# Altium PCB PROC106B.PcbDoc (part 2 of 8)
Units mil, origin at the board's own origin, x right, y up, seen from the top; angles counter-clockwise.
Board outline 4498.18 x 1060.53 mil, 8 copper layers (Top Layer, GND1, Sig1, PWR1, PWR2, Sig2, GND2, Bottom Layer), stack 69.602 mil thick; 439 components, 327 nets, 1548 pads, 843 vias.
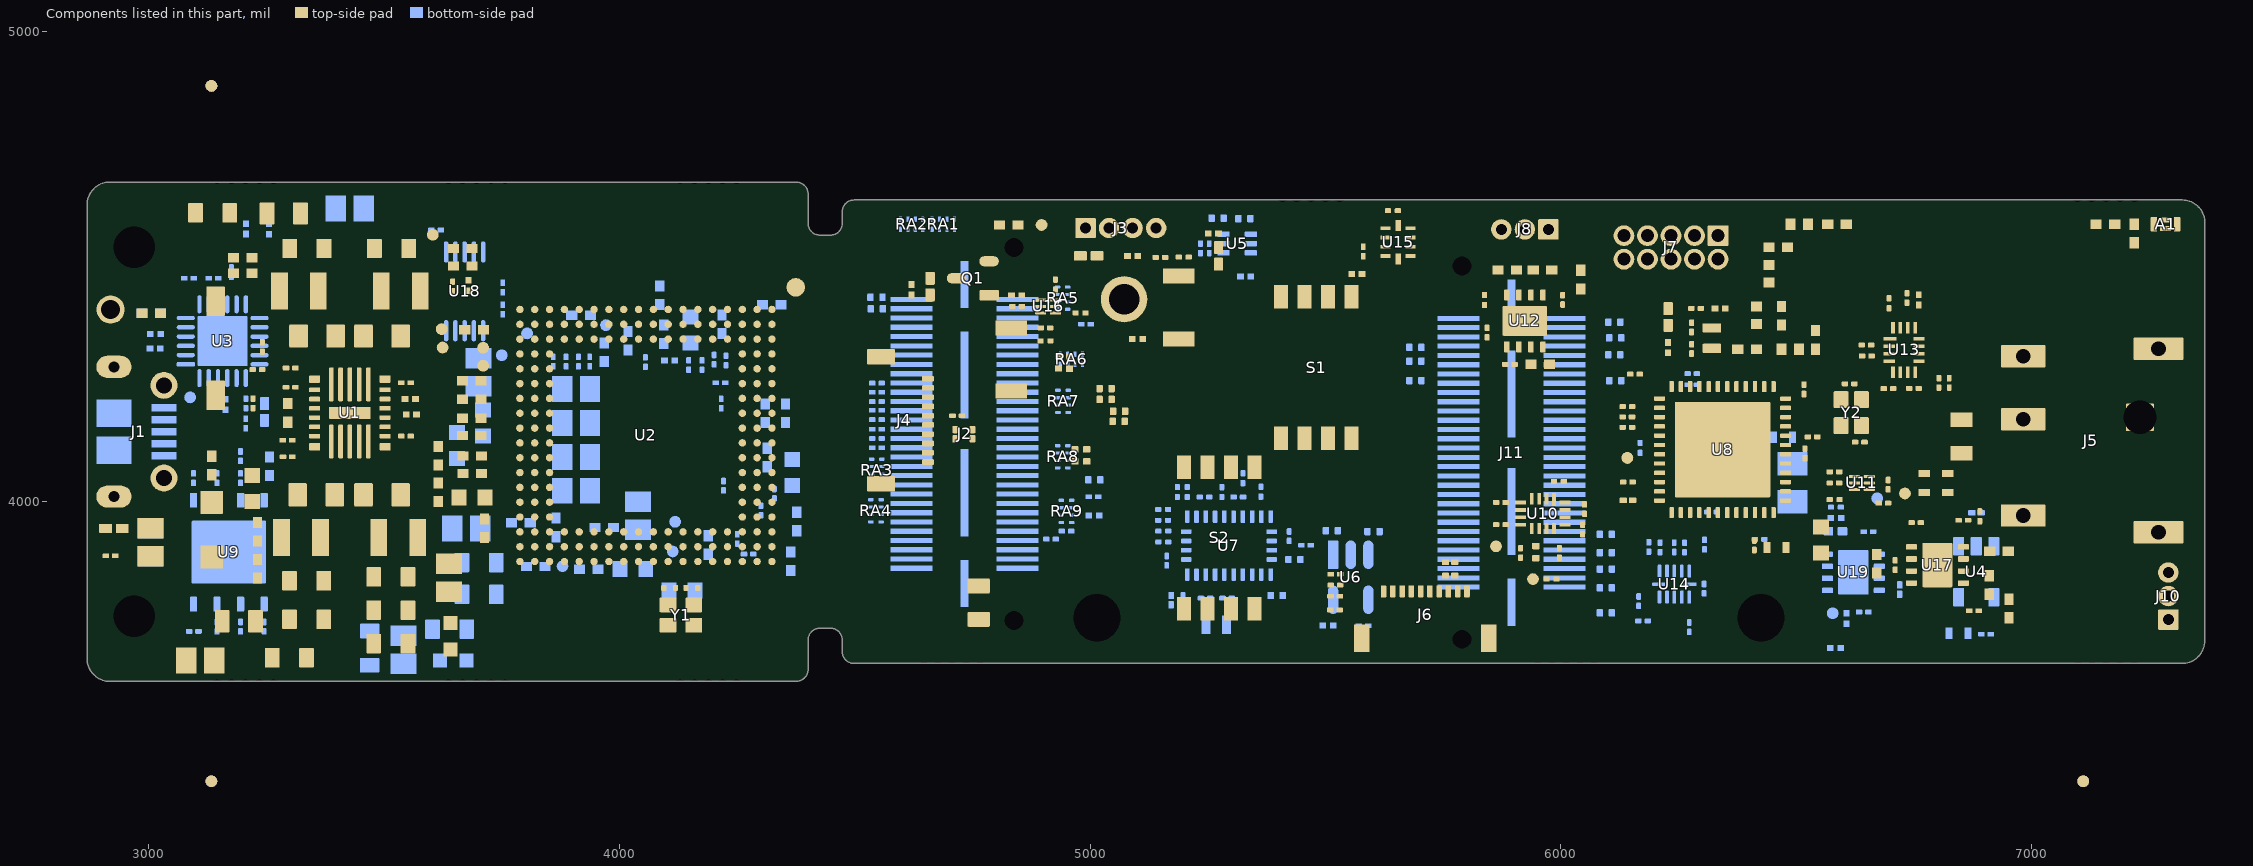
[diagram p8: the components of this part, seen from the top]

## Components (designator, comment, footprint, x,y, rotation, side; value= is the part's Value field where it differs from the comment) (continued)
R122 "RR0306P-103-D" FP-RR0306P-103-D_0201-IPC_C#1 5837.64,4429.06 r270 top
R123 "RC0201JR-070RL" "FP-RC0201JR-070RL_0201 (0603 METRIC)-IPC_C" 5843.14,4359.71 r90 top
R124 "RR0306P-103-D" FP-RR0306P-103-D_0201-IPC_C#1 4905.31,4342.12 r0 top
R125 "RR0306P-103-D" FP-RR0306P-103-D_0201-IPC_C#1 5198.85,4520.03 r180 top
R126 "CRCW040261R9FKED" 0402L 5960.92,4492.48 r0 top value=61.9
R127 "RC0201JR-070RL" "FP-RC0201JR-070RL_0201 (0603 METRIC)-IPC_C" 6649.8,4310 r0 top
R128 "RC0201JR-070RL" "FP-RC0201JR-070RL_0201 (0603 METRIC)-IPC_C" 6695.72,4240.71 r180 top
R129 "RC0201JR-070RL" "FP-RC0201JR-070RL_0201 (0603 METRIC)-IPC_C" 5149.26,4519.45 r180 top
R130 "AC0201FR-0720RL" FP-AC0201FR-0720RL_0201-IPC_C 4547.27,4134.63 r0 bottom
R131 "RC0201JR-070RL" "FP-RC0201JR-070RL_0201 (0603 METRIC)-IPC_C" 6321.17,3978.41 r180 bottom
R132 "AC0201FR-0720RL" FP-AC0201FR-0720RL_0201-IPC_C 4547.27,4154.34 r0 bottom
R133 "AC0201FR-0720RL" FP-AC0201FR-0720RL_0201-IPC_C 4547.27,4174.75 r0 bottom
R134 "RR0306P-103-D" FP-RR0306P-103-D_0201-IPC_C#1 6889.73,3969.51 r90 top
R135 "AC0201FR-0720RL" FP-AC0201FR-0720RL_0201-IPC_C 4547.27,4194.78 r0 bottom
R136 "RC0201JR-070RL" "FP-RC0201JR-070RL_0201 (0603 Metric)-IPC_C" 6749.82,4241 r0 top
R137 "AC0201FR-0720RL" FP-AC0201FR-0720RL_0201-IPC_C 4547.27,4213.11 r0 bottom
R138 "AC0201FR-0720RL" FP-AC0201FR-0720RL_0201-IPC_C 4547.27,4233.08 r0 bottom
R139 "RC0201JR-070RL" "FP-RC0201JR-070RL_0201 (0603 Metric)-IPC_C" 6824.81,4252.99 r270 top
R140 "AC0201FR-0720RL" FP-AC0201FR-0720RL_0201-IPC_C 4547.27,4252.4 r0 bottom
R141 "RC0201FR-074K99L" 0201L 6760.03,4429.26 r90 top value=4.99k
R142 "RC0201JR-070RL" "FP-RC0201JR-070RL_0201 (0603 Metric)-MFG" 4992.71,4098.76 r270 top
R143 "RC0201JR-070RL" "FP-RC0201JR-070RL_0201 (0603 Metric)-MFG" 4967.77,4098.76 r270 top
R144 "RC0201JR-070RL" "FP-RC0201JR-070RL_0201 (0603 Metric)-MFG" 5061.58,4192.66 r0 top
R145 "RC0201JR-070RL" "FP-RC0201JR-070RL_0201 (0603 Metric)-MFG" 5060.48,4171.22 r0 top
R146 "RC0201JR-070RL" "FP-RC0201JR-070RL_0201 (0603 Metric)-MFG" 5032.8,4217.79 r0 top
R147 "RC0201JR-070RL" "FP-RC0201JR-070RL_0201 (0603 Metric)-MFG" 5032.8,4240.79 r0 top
R148 "RC0201JR-070RL" "FP-RC0201JR-070RL_0201 (0603 Metric)-MFG" 4932.76,4296.62 r90 top
R149 "RC0201JR-070RL" "FP-RC0201JR-070RL_0201 (0603 Metric)-MFG" 4956.17,4295.87 r90 top
R150 "RC0201JR-070RL" "FP-RC0201JR-070RL_0201 (0603 Metric)-MFG" 6113.61,4381.76 r0 bottom
R151 "RC0201JR-070RL" "FP-RC0201JR-070RL_0201 (0603 Metric)-MFG" 6115.41,4348.48 r0 bottom
R152 "RC0201JR-070RL" "FP-RC0201JR-070RL_0201 (0603 Metric)-MFG" 5690.93,4328.4 r0 bottom
R153 "RC0201JR-070RL" "FP-RC0201JR-070RL_0201 (0603 Metric)-MFG" 6113.32,4312.59 r0 bottom
R154 "RC0201JR-070RL" "FP-RC0201JR-070RL_0201 (0603 Metric)-MFG" 5690.93,4298.93 r0 bottom
R155 "RC0201JR-070RL" "FP-RC0201JR-070RL_0201 (0603 Metric)-MFG" 6115.55,4257.57 r0 bottom
R157 "RC0201JR-070RL" "FP-RC0201JR-070RL_0201 (0603 Metric)-MFG" 5690.93,4257.72 r0 bottom
R158 "ERJ-1GNF8252C" FP-ERJ-1GNF8252C_0201-IPC_C 4175.56,4290.74 r270 bottom value=82.5k
R159 "ERJ-1GNJ751C" FP-ERJ-1GNJ751C_0201-IPC_C 4201.23,4302.15 r90 bottom value=750
R160 "RC0201JR-070RL" "FP-RC0201JR-070RL_0201 (0603 METRIC)-IPC_C" 6262.64,3903.15 r90 bottom
R161 "RC0201JR-070RL" "FP-RC0201JR-070RL_0201 (0603 METRIC)-IPC_C" 6141.18,4158.46 r0 top
R166 "RC0201JR-070RL" "FP-RC0201JR-070RL_0201 (0603 METRIC)-IPC_C" 6240.62,3903.59 r90 bottom
R168 "RC0201JR-070RL" "FP-RC0201JR-070RL_0201 (0603 METRIC)-IPC_C" 6186.75,3904.39 r90 bottom
R170 "ERJ-1GNF8252C" FP-ERJ-1GNF8252C_0201-IPC_C 4214.74,4253.13 r180 bottom value=82.5k
R171 "ERJ-1GNJ751C" FP-ERJ-1GNJ751C_0201-IPC_C 4226.45,4300.41 r90 bottom value=750
R172 "ERJ-1GNF8252C" FP-ERJ-1GNF8252C_0201-IPC_C 3206.71,4209.45 r270 bottom value=82.5k
R174 "ERJ-1GNF7871C" FP-ERJ-1GNF7871C_0201-IPC_C 4147.23,4290.74 r270 bottom value=7.87k
R176 "ERJ-1GNF7871C" FP-ERJ-1GNF7871C_0201-IPC_C 3221.71,4209.45 r270 top value=7.87k
R177 "RR0306P-103-D" FP-RR0306P-103-D_0201-IPC_C#1 4979.62,4401.5 r180 top
R178 "RR0306P-103-D" FP-RR0306P-103-D_0201-IPC_C#1 4926.29,4461.7 r270 top
R180 "ERJ-1GNF4701C" FP-ERJ-1GNF4701C_0201-IPC_C 6165.19,3789.15 r270 bottom
R181 "ERJ-1GNF4701C" FP-ERJ-1GNF4701C_0201-IPC_C 5520.05,3770.65 r180 top
R182 "RC0201JR-070RL" "FP-RC0201JR-070RL_0201 (0603 METRIC)-IPC_C" 4717.71,4183.18 r180 top
R183 "RC0201JR-070RL" "FP-RC0201JR-070RL_0201 (0603 METRIC)-IPC_C" 5520.61,3799.62 r180 top
R184 "RC0201JR-070RL" "FP-RC0201JR-070RL_0201 (0603 METRIC)-IPC_C" 5521.16,3823.28 r180 top
R185 "RC0201JR-070RL" "FP-RC0201JR-070RL_0201 (0603 METRIC)-IPC_C" 5521,3846.49 r180 top
R186 "RC0201JR-070RL" "FP-RC0201JR-070RL_0201 (0603 Metric)-MFG" 6095.54,3931.22 r0 bottom
R187 "RC0201JR-070RL" "FP-RC0201JR-070RL_0201 (0603 Metric)-MFG" 6095.54,3892.26 r0 bottom
R188 "RC0201JR-070RL" "FP-RC0201JR-070RL_0201 (0603 Metric)-MFG" 6095.54,3857.41 r0 bottom
R189 "RC0201JR-070RL" "FP-RC0201JR-070RL_0201 (0603 Metric)-MFG" 6095.54,3817.56 r0 bottom
R190 "RC0201JR-070RL" "FP-RC0201JR-070RL_0201 (0603 Metric)-MFG" 6095.54,3764.53 r0 bottom
RA1 "EXB-18VR000X" FP-EXB-18VR000X_0502-MFG 4688.09,4589.75 r0 bottom
RA2 "EXB-18VR000X" FP-EXB-18VR000X_0502-MFG 4620.86,4589.75 r0 bottom
RA3 "EXB-18VR000X" FP-EXB-18VR000X_0502-MFG 4546.77,4067.23 r90 bottom
RA4 "EXB-18VR000X" FP-EXB-18VR000X_0502-MFG 4545.1,3981.11 r90 bottom
RA5 "EXB-18VR000X" FP-EXB-18VR000X_0502-MFG 4941.51,4432.71 r90 bottom locked
RA6 "EXB-18VR000X" FP-EXB-18VR000X_0502-MFG 4960.21,4302.91 r0 bottom
RA7 "EXB-18VR000X" FP-EXB-18VR000X_0502-MFG 4942.52,4213.65 r90 bottom locked
RA8 "EXB-18VR000X" FP-EXB-18VR000X_0502-MFG 4941.86,4095.87 r90 bottom locked
RA9 "EXB-18VR000X" FP-EXB-18VR000X_0502-MFG 4949.85,3979.76 r90 bottom locked
S1 "218-4LPST" SW_218-4LPST 5480.37,4285.46 r90 top
S2 "218-4LPST" SW_218-4LPST 5274.37,3923.46 r90 top locked
S3 "CHS-01TA" FP-CHS-01TA_SMT_SW_5MM4_2MM5-MFG 3142.31,4326.42 r90 top
SW2 "B3U-1000P" SW_B3U-1000P 4832.84,4302.77 r270 top
SW3 "B3U-1000P" SW_B3U-1000P 5188.73,4412.81 r270 top
TP2 "TESTPOINT" TP_25MIL-SMT 4113.44,3894.78 r180 bottom
TP3 "TESTPOINT" TP_25MIL-SMT 4118.39,3957.8 r180 bottom
TP4 "TESTPOINT" TP_25MIL-SMT 6671.71,4007.65 r180 bottom
TP5 "TESTPOINT" TP_25MIL-SMT 3603.84,4567.52 r180 top
TP6 "TESTPOINT" TP_25MIL-SMT 3750.12,4311.58 r90 bottom
TP7 "TESTPOINT" TP_25MIL-SMT 3804,4358 r0 bottom
TP8 "TESTPOINT" TP_25MIL-SMT 3710.6,4327.53 r0 top
TP9 "TESTPOINT" TP_25MIL-SMT 3710.6,4289.4 r0 top
TP10 "TESTPOINT" TP_25MIL-SMT 6577.18,3763.46 r270 bottom
TP11 "TP_SM_1MM" TP_SM_1MM 4374.76,4455.87 r180 top
TP12 "TESTPOINT" TP_VIA_060RND040 2919.28,4408.64 r90 top
TP13 "TESTPOINT" TP_25MIL-SMT 4896.84,4588.36 r270 top
TP14 "TESTPOINT" TP_25MIL-SMT 3971.52,4375.57 r270 bottom
TP15 "TESTPOINT" TP_25MIL-SMT 6730.81,4018 r90 top
TP16 "TESTPOINT" TP_25MIL-SMT 6141.18,4093.46 r180 top
TP17 "TESTPOINT" TP_25MIL-SMT 3879.25,3863.39 r180 bottom
TP18 "TESTPOINT" TP_25MIL-SMT 3622.56,4367.08 r180 top
TP19 "TESTPOINT" TP_25MIL-SMT 3624.53,4327.96 r180 top
TP20 "4953" FP-4953_HDR1-MFG 5072.16,4430.47 r180 bottom locked
TP26 "TESTPOINT" TP_25MIL-SMT 3088.22,4222.02 r0 bottom
TP27 "TESTPOINT" TP_25MIL-SMT 5862.18,3905.74 r270 top
TP46 "TESTPOINT" TP_25MIL-SMT 5940.71,3836.09 r270 top
U1 "LP87524JRNFRQ1" RNF0026C 3427.48,4189 r180 top
U2 "AWR1843AoPBGALP" ALP0180A-MFG 4056.48,4141.13 r180 top
U3 "CP2105-F01-GMR" FP-CP2105-F01-GMR_QFN24-EP-IPC_A 3157.31,4341.42 r0 bottom
U4 "TPS79330DBVR" DBV0005A_N 6882.18,3851.63 r270 bottom
U5 "TMP112AQDRLRQ1" DRL0006A 5312.36,4548.71 r180 bottom
U6 "CAT24C08TDI-GT3" FP-CAT24C08TDI-GT3_TSOT-23-5-IPC_A 5553.54,3840.01 r270 bottom
U7 "BNO085" FP-BNO085_LGA28-MFG 5294.88,3907.22 r270 bottom
U8 "CC2642R1FRGZR" RGZ0048A 6343.38,4111.11 r270 top
U9 "MX25V1635FZNQ" WSON-8L_6x5MM_EP 3170.35,3893.29 r90 bottom locked
U10 "TCA6408ARSVR" RSV0016A 5961.56,3975.2 r270 top
U11 "SN74LVC1G3157DSFR" DSF0006A 6639.32,4040.29 r180 top
U12 "TCAN1042HGVDRBRQ1" DRB0008F 5923.44,4384.46 r90 top
U13 "TS3A5018RSVR" RSV0016A 6728.94,4322.76 r0 top
U14 "TXB0104QRUTRQ1" RUT0012A 6241.04,3825.36 r90 bottom
U15 "TS5A23157RSER" RSE0010A 5654.19,4551.79 r180 top
U16 "SN74LVC1G11DSFR" DSF0006A-MFG 4910.54,4415.28 r180 top
U17 "TCAN1042HGVDRBRQ1" DRB0008F 6799.78,3866 r0 top
U18 "TS5A23157QDGSRQ1" DGS0010A_L 3671.35,4447.33 r270 bottom
U19 "TPS2115ADRBR" DRB0008B 6621.18,3850.46 r0 bottom
Y1 "FW4000044Q" FP-FW4000044Q_4-SMD-2.0x1.6mm-MFG 4130.76,3759.63 r180 top
Y2 "CX2016DB48000C0WPLA2" FP-CX2016DB48000C0WPLA2_SMD4-MFG 6616.71,4189.85 r270 top
Y3 "ABS05W-32.768KHZ-D-2-T" FP-ABS05W-32.768KHZ-D-2-T_XTAL_SMT_1MM6_1MM0-MFG 6320.71,4347.93 r270 top
Y4 "ABS05W-32.768KHZ-D-2-T" FP-ABS05W-32.768KHZ-D-2-T_XTAL_SMT_1MM6_1MM0-MFG 5267.82,3738.88 r0 bottom
ZZ1 "This Assembly Note is for PCB labels only" AssemblyNoteLabel 2349.62,2814.36 r0 top
ZZ2 "These assemblies are ESD sensitive, ESD precautions shall be observed." AssemblyNote 2346.49,2738.89 r0 top
ZZ3 "These assemblies must be clean and free from flux and all contaminants. Use of no clean flux is not acceptable." AssemblyNote 2346.43,2653.5 r0 top
ZZ4 "These assemblies must comply with workmanship standards IPC-A-610 Class 2, unless otherwise specified." AssemblyNote 2343.34,2567.2 r0 top
ZZ5.1 "Cut the thermal pad(Part Number#GPVOUS-0.125-AC-0816) for the shape and size of the inner surface of the heatsink(Part Number#MCH065) and paste it on the inner surface of the heatsink;" AssemblyNote 2340.76,2492.7 r0 top
ZZ5.2 "Bring the heatsink onto the PCB bottom side (Opposite side of AOP device). Match the teeth in the heatsink with break-away area in the PCB and press the heatsink onto the PCB slightly so as thermal pad is spread all over the area" AssemblyNote 2343.41,2409 r0 top

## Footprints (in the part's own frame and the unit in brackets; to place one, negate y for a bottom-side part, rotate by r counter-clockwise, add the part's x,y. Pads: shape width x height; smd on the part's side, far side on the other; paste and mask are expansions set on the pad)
0201L [mm] "Data from Kemet datasheet CC101_COM dated 7/28/11"
  rect 0.36x0.32 smd mask+0.048: 1(-0.28,0) 2(0.28,0)
  body extent -0.31,-0.16 0.31,0.16, height 0.26
0402_070 [mil] "SMD, 2-Leads, Body 1.2x0.7mm, Height 0.7mm"
  rect 15x24 smd: 1(-20,0) 2(20,0)
  body extent -24,-14 24,14, height 28
0402L [mm] "0402 from SM-752 data"
  rect 0.6x0.5 smd: 1(-0.5,0) 2(0.5,0)
  body extent -0.55,-0.3 0.55,0.3, height 0.6
0402S [mil] "Based on C0402S footprint from PADS legacy"
  rect 15x24 smd: 1(-20,0) 2(20,0)
  body extent -22,-12 22,12, height 24
0603_HV [mil] "Ernesto recommended land pattern.  26 mil between pads."
  rect 30x30 smd: 1(-28,0) 2(28,0)
  silkscreen extent -52,-24 52,24, body extent -34,-19 34,19, height 39
0603L [mm] "0603 from SM-752 data"
  rect 0.8x0.85 smd: 1(-0.7,0) 2(0.7,0)
  silkscreen extent -0.07,-0.33 0.07,0.33, body extent -0.87,-0.47 0.87,0.47, height 1
0805_HV [mil] "0805 with 30mil clearance between pads"
  rect 50x63 smd: 1(-40,0) 2(40,0)
  silkscreen extent -74,-40 74,40, body extent -43,-29 43,29, height 57
0805_HV1 [mm] "Custom footprint based on analyzing multiple manufacturer recommendations"
  rrect10% 1x1.25 smd: 1(-1,0) 2(1,0)
  silkscreen extent -0.2,-0.75 0.2,0.75, body extent -1.1,-0.72 1.1,0.73, height 1.45
0805L [mm] "0805 from SM-752 data"
  rect 1.1x1.4 smd: 1(-0.75,0) 2(0.75,0)
  body extent -1.1,-0.72 1.1,0.72, height 1.45
ALP0180A-MFG [mm]
  round 0.4 smd paste+0 mask-1000: A1(-6.8,6.8) A2(-6,6.8) A3(-5.2,6.8) A4(-4.4,6.8) A5(-3.6,6.8) A6(-2.8,6.8) A7(-2,6.8) A8(-1.2,6.8) A9(-0.4,6.8) A10(0.4,6.8) A11(1.2,6.8) A12(2,6.8) A13(2.8,6.8) A14(3.6,6.8) A15(4.4,6.8) A16(5.2,6.8) A17(6,6.8) A18(6.8,6.8) B1(-6.8,6) B2(-6,6) B3(-5.2,6) B4(-4.4,6) B5(-3.6,6) B6(-2.8,6) B7(-2,6) B8(-1.2,6) B9(-0.4,6) B10(0.4,6) B11(1.2,6) B12(2,6) B13(2.8,6) B14(3.6,6) B15(4.4,6) B16(5.2,6) B17(6,6) B18(6.8,6) C1(-6.8,5.2) C2(-6,5.2) C3(-5.2,5.2) C4(-4.4,5.2) C5(-3.6,5.2) C6(-2.8,5.2) C7(-2,5.2) C8(-1.2,5.2) C9(-0.4,5.2) C10(0.4,5.2) C11(1.2,5.2) C12(2,5.2) C13(2.8,5.2) C14(3.6,5.2) C15(4.4,5.2) C16(5.2,5.2) C17(6,5.2) C18(6.8,5.2) D1(-6.8,4.4) D2(-6,4.4) D3(-5.2,4.4) D16(5.2,4.4) D17(6,4.4) D18(6.8,4.4) E1(-6.8,3.6) E2(-6,3.6) E3(-5.2,3.6) E16(5.2,3.6) E17(6,3.6) E18(6.8,3.6) F1(-6.8,2.8) F2(-6,2.8) F3(-5.2,2.8) F16(5.2,2.8) F17(6,2.8) F18(6.8,2.8) G1(-6.8,2) G2(-6,2) G3(-5.2,2) G16(5.2,2) G17(6,2) G18(6.8,2) H1(-6.8,1.2) H2(-6,1.2) H3(-5.2,1.2) H16(5.2,1.2) H17(6,1.2) H18(6.8,1.2) J1(-6.8,0.4) J2(-6,0.4) J3(-5.2,0.4) J16(5.2,0.4) J17(6,0.4) J18(6.8,0.4) K1(-6.8,-0.4) K2(-6,-0.4) K3(-5.2,-0.4) K16(5.2,-0.4) K17(6,-0.4) K18(6.8,-0.4) L1(-6.8,-1.2) L2(-6,-1.2) L3(-5.2,-1.2) L16(5.2,-1.2) L17(6,-1.2) L18(6.8,-1.2) M1(-6.8,-2) M2(-6,-2) M3(-5.2,-2) M16(5.2,-2) M17(6,-2) M18(6.8,-2) N1(-6.8,-2.8) N2(-6,-2.8) N3(-5.2,-2.8) N16(5.2,-2.8) N17(6,-2.8) N18(6.8,-2.8) P1(-6.8,-3.6) P2(-6,-3.6) P3(-5.2,-3.6) P16(5.2,-3.6) P17(6,-3.6) P18(6.8,-3.6) R1(-6.8,-4.4) R2(-6,-4.4) R3(-5.2,-4.4) R16(5.2,-4.4) R17(6,-4.4) R18(6.8,-4.4) T1(-6.8,-5.2) T2(-6,-5.2) T3(-5.2,-5.2) T4(-4.4,-5.2) T5(-3.6,-5.2) T6(-2.8,-5.2) T7(-2,-5.2) T8(-1.2,-5.2) T9(-0.4,-5.2) T10(0.4,-5.2) T11(1.2,-5.2) T12(2,-5.2) T13(2.8,-5.2) T14(3.6,-5.2) T15(4.4,-5.2) T16(5.2,-5.2) T17(6,-5.2) T18(6.8,-5.2) U1(-6.8,-6) U2(-6,-6) U3(-5.2,-6) U4(-4.4,-6) U5(-3.6,-6) U6(-2.8,-6) U7(-2,-6) U8(-1.2,-6) U9(-0.4,-6) U10(0.4,-6) U11(1.2,-6) U12(2,-6) U13(2.8,-6) U14(3.6,-6) U15(4.4,-6) U16(5.2,-6) U17(6,-6) U18(6.8,-6) V1(-6.8,-6.8) V2(-6,-6.8) V3(-5.2,-6.8) V4(-4.4,-6.8) V5(-3.6,-6.8) V6(-2.8,-6.8) V7(-2,-6.8) V8(-1.2,-6.8) V9(-0.4,-6.8) V10(0.4,-6.8) V11(1.2,-6.8) V12(2,-6.8) V13(2.8,-6.8) V14(3.6,-6.8) V15(4.4,-6.8) V16(5.2,-6.8) V17(6,-6.8) V18(6.8,-6.8)
  silkscreen extent -8.3,-7.55 7.55,7.55, body extent -8.05,-8.05 8.05,8.05, height 0.25
APHHS1005_Green [mm] "SMD, 2-Leads, Body 1x0.5mm"
  rrect20% 0.7x0.5 smd: 1(-0.45,0) 2(0.45,0)
  silkscreen extent -0.8,-0.65 1.12,0.65, body extent -0.5,-0.25 0.5,0.25, height 0.5
AssemblyNote [mil] "Assembly Note"
AssemblyNoteLabel [mil] "Assembly Note for PCB Labels"
BRAKE_WAY_HOLES1X2 [mil]
CONN_105017-0001 [mm] "Molex Micro USB-B"
  rect 0.4x1.35 smd: 1(-1.3,1.35) 2(-0.65,1.35) 3(0,1.35) 4(0.65,1.35) 5(1.3,1.35)
  oval 1.2x1.9 hole 0.6 slot 1.3 at 90 deg: 6(-3.5,-1.35) 9(3.5,-1.35)
  rect 1.5x1.9 smd: 7(-1,-1.35) 8(1,-1.35)
  round 1.45 hole 0.85: 10(2.5,1.35) 11(-2.5,1.35)
  Top Layer region: 3.5,-2.3 2.3,-2.3 2.3,-0.4 3.5,-0.4
  Top Layer region: -3.5,-0.4 -2.3,-0.4 -2.3,-2.3 -3.5,-2.3
  silkscreen extent -4.1,-0.2 4.1,1.4, body extent -4.1,-3.93 4.1,1.5, height 2.72
CUI_PJ-051AH [mm] "DC Power Jack, R/A, TH"
  rrect8% 2.4x1.2 hole 0.8 square: 1(-6.3,3.3) 2(-6.3,-5.3) 3(-6.3,-0.1)
  rrect8% 2.7x1.2 hole 0.8 square: 4(1,-6.2) 5(1,3.7)
  rrect7% 1.5x1.5 hole 1.8 square unplated mask+0.102: MH1(0,0)
  body extent -7.75,-6.3 4,3.8, height 7.31
DBV0005A_N [mm] "SOT23, 5-Leads, Body 2.9x1.6mm, Pitch 0.95mm, Lead Span 2.8mm, IPC Medium Density"
  rrect17% 1x0.6 smd: 1(-1.375,0.95) 2(-1.375,0) 3(-1.375,-0.95) 4(1.375,-0.95) 5(1.375,0.95)
  silkscreen extent -0.25,-1.55 0.25,1.55, body extent -1.42,-1.46 1.42,1.46, height 1.09
DFE252012P [mm] "TOKO, Pad sizes increased as per request"
  rect 0.9x2 smd: 1(-1.05,0) 2(1.05,0)
  silkscreen extent -0.3,-1.2 0.3,1.2, body extent -1.35,-1.1 1.35,1.1, height 1.2
DGS0010A_L [mm] "TSSOP, 10-Leads, Body 3x3mm, Pitch 0.5mm, IPC High Density"
  oval 1.15x0.25 smd: 1(-2.125,1) 2(-2.125,0.5) 3(-2.125,0) 4(-2.125,-0.5) 5(-2.125,-1) 6(2.125,-1) 7(2.125,-0.5) 8(2.125,0) 9(2.125,0.5) 10(2.125,1)
  silkscreen extent -2.65,-1.55 0.9,1.55, body extent -2.45,-1.5 2.45,1.5, height 0.96
DRB0008B [mm] "SON, 8-Leads, Body 3x3mm, Pitch 0.65mm, Thermal Pad 2.4x1.65mm, TI Recommended"
  rrect33% 0.6x0.3 smd: 1(-1.4,0.975) 2(-1.4,0.325) 3(-1.4,-0.325) 4(-1.4,-0.975) 5(1.4,-0.975) 6(1.4,-0.325) 7(1.4,0.325) 8(1.4,0.975)
  rrect9% 1.47x1.06 on Bottom Paste: 9(0,-0.63) 9(0,0.63)
  rrect6% 1.65x2.4 smd paste-1.2: 9(0,0)
  silkscreen extent -1.73,-1.73 1.73,1.73, body extent -1.5,-1.5 1.5,1.5, height 0.96
DRB0008F [mm] "SON, 8-Leads, Body 3x3mm, Pitch 0.65mm, Thermal Pad 2.4x1.6mm, TI Recommended"
  rrect33% 0.6x0.3 smd: 1(-1.4,0.975) 2(-1.4,0.325) 3(-1.4,-0.325) 4(-1.4,-0.975) 5(1.4,-0.975) 6(1.4,-0.325) 7(1.4,0.325) 8(1.4,0.975)
  rrect9% 1.47x1.07 on Top Paste: 9(0,0.635) 9(0,-0.635)
  rrect6% 1.6x2.4 smd paste-1.2: 9(0,0)
  silkscreen extent -1.73,-1.73 1.73,1.73, body extent -1.5,-1.5 1.5,1.5, height 0.77
DRL0006A [mm] "SOTFL, 6-Flat Leads, Body 1.2x1.6x0.6mm, Pitch 0.5mm, TI recommended"
  rrect33% 0.67x0.3 smd: 1(-0.74,0.5) 2(-0.74,0) 3(-0.74,-0.5) 4(0.74,-0.5) 5(0.74,0) 6(0.74,0.5)
  silkscreen extent -0.9,-0.95 0.5,0.95, body extent -0.8,-0.8 0.8,0.8, height 0.61
DSF0006A [mm] "TI recommended land pattern"
  rrect59% 0.6x0.17 smd mask+0.045: 1(-0.4,0.35) 2(-0.4,0) 3(-0.4,-0.35) 4(0.4,-0.35) 5(0.4,0) 6(0.4,0.35)
  silkscreen extent -0.6,-0.63 0.6,0.63, body extent -0.5,-0.5 0.5,0.5, height 0.48
DSF0006A-MFG [mm]
  rrect59% 0.6x0.17 smd paste+0 mask+0: 1(-0.4,0.35) 2(-0.4,0) 3(-0.4,-0.35) 4(0.4,-0.35) 5(0.4,0) 6(0.4,0.35)
  silkscreen extent -1.14,-0.85 0.53,1.02, body extent -0.8,-0.63 0.8,0.63, height 0.25
FIDUCIAL6.4-20 [mil]
  round 25 smd mask+26.87: 1(0,0)
FP-250R05L120JV4T_0201-IPC_C [mm]
  rrect38% 0.363x0.263 smd paste+0 mask+0: 1(-0.25,0) 2(0.25,0)
  body extent -0.53,-0.27 0.53,0.26, height 0.25
FP-4953_HDR1-MFG [mm]
  round 2.5 hole 1.65 paste-1000 mask+0: 1(0,0)
  body extent -1.24,-0.25 1.24,0.25, height 9.16
FP-51441-1093_CONN_SMD_FFC-0 [mm]
  rrect33% 0.3x0.65 smd paste+0 mask+0: 1(-2.25,1.775) 2(-1.75,1.775) 3(-1.25,1.775) 4(-0.75,1.775) 5(-0.25,1.775) 6(0.25,1.775) 7(0.75,1.775) 8(1.25,1.775) 9(1.75,1.775) 10(2.25,1.775)
  rrect12% 0.85x1.5 smd paste+0 mask+0: 11(-3.425,-0.75) 12(3.425,-0.75)
  body extent -3.95,-1.9 3.95,2.2, height 0.25
FP-ABS05W-32.768KHZ-D-2-T_XTAL_SMT_1MM6_1MM0-MFG [mm]
  rrect20% 0.5x1 smd paste+0 mask+0: 1(-0.55,0) 2(0.55,0)
  body extent -0.95,-0.65 0.95,0.65, height 0.25
FP-AC0201FR-0720RL_0201-IPC_C [mil]
  rrect38% 13.94x10.34 smd paste+0 mask+0: 1(-10.01,0) 2(10.01,0)
  body extent -12,-6 12,6, height 10
FP-ANT016008LCS2442MA2_SMT_ANT-0 [mm]
  rrect29% 0.35x0.8 smd paste+0 mask+0.038: 1(-0.625,0) 4(0.625,0)
  rrect38% 0.6x0.26 smd paste+0 mask+0.038: 2-3(0,-0.235) 5-6(0,0.235)
  body extent -0.95,-0.55 0.95,0.55, height 0.25
FP-BNO085_LGA28-MFG [mm]
  rrect40% 0.675x0.25 smd paste+0 mask+0: 1(1.562,2.25) 6(-1.562,2.25) 7(-1.562,1.75) 8(-1.562,1.25) 9(-1.562,0.75) 10(-1.562,0.25) 11(-1.562,-0.25) 12(-1.562,-0.75) 13(-1.562,-1.25) 14(-1.562,-1.75) 15(-1.562,-2.25) 20(1.562,-2.25) 21(1.562,-1.75) 22(1.562,-1.25) 23(1.562,-0.75) 24(1.562,-0.25) 25(1.562,0.25) 26(1.562,0.75) 27(1.562,1.25) 28(1.562,1.75)
  rrect40% 0.25x0.575 smd paste+0 mask+0: 2(0.75,2.312) 3(0.25,2.312) 4(-0.25,2.312) 5(-0.75,2.312) 16(-0.75,-2.312) 17(-0.25,-2.312) 18(0.25,-2.312) 19(0.75,-2.312)
  body extent -1.9,-2.6 1.9,2.6, height 1.18
FP-BSS123-7-F_SOT23-IPC_C [mm]
  rrect18% 1.059x0.547 smd paste+0 mask+0: 1(-0.877,0.915)
  rrect100% 1.059x0.547 smd paste+0 mask+0: 2(-0.877,-0.915) 3(0.877,0)
  body extent -1.51,-1.55 1.51,1.55, height 0.25
FP-CAT24C08TDI-GT3_TSOT-23-5-IPC_A [mm]
  rrect18% 1.54x0.566 smd paste+0 mask+0: 1(-1.216,0.95)
  rrect100% 1.54x0.566 smd paste+0 mask+0: 2(-1.216,0) 3(-1.216,-0.95) 4(1.216,-0.95) 5(1.216,0.95)
  body extent -1.4,-1.45 1.4,1.45, height 1
FP-CGA1A2C0G1H4R7C030BA_0201-IPC_C [mil]
  rrect35% 11.14x12.52 smd paste+0 mask+0: 1(-12.5,0) 2(12.5,0)
  silkscreen extent -18,-24 18,14, body extent -22,-12 22,12, height 10
FP-CGA4J1X7T0J226M125AC_0805-MFG [mm]
  rrect13% 0.8x1.05 smd paste+0 mask+0: 1(-0.925,0) 2(0.925,0)
  silkscreen extent -0.15,-0.77 0.15,0.77, body extent -1.43,-0.87 1.43,0.87, height 0.25
FP-CHS-01TA_SMT_SW_5MM4_2MM5-MFG [mm]
  rrect10% 1.6x1 smd paste+0 mask+0: 1(-2.54,0) 2(2.54,0)
  body extent -2.8,-1.25 2.8,1.25, height 2.5
FP-CL03A103KA3NNNC_0201-IPC_C [mil]
  rrect38% 13.94x10.34 smd paste+0 mask+0: 1(-10.01,0) 2(10.01,0)
  body extent -12,-6 12,6, height 15
FP-CL03A105MO3NRNH_0201-IPC_C [mil]
  rrect33% 15.83x11.94 smd paste+0 mask+0: 1(-9.87,0) 2(9.87,0)
  body extent -12,-6 12,6, height 15
FP-CP2105-F01-GMR_QFN24-EP-IPC_A [mm]
  rrect42% 0.979x0.239 smd paste+0 mask+0: 1(-1.99,1.25)
  rrect100% 0.979x0.239 smd paste+0 mask+0: 2(-1.99,0.75) 3(-1.99,0.25) 4(-1.99,-0.25) 5(-1.99,-0.75) 6(-1.99,-1.25) 13(1.99,-1.25) 14(1.99,-0.75) 15(1.99,-0.25) 16(1.99,0.25) 17(1.99,0.75) 18(1.99,1.25)
  rrect100% 0.239x0.979 smd paste+0 mask+0: 7(-1.25,-1.99) 8(-0.75,-1.99) 9(-0.25,-1.99) 10(0.25,-1.99) 11(0.75,-1.99) 12(1.25,-1.99) 19(1.25,1.99) 20(0.75,1.99) 21(0.25,1.99) 22(-0.25,1.99) 23(-0.75,1.99) 24(-1.25,1.99)
  rrect4% 2.7x2.7 smd paste-1000 mask+0: 25(0,0)
  body extent -2,-2 2,2, height 0.8
FP-CRCW0402200RFKEDHP_0402-IPC_C [mil]
  rrect21% 20.29x18.6 smd paste+0 mask+0: 1(-14.9,0) 2(14.9,0)
  body extent -20,-10 20,10, height 16
FP-CX2016DB48000C0WPLA2_SMD4-MFG [mm]
  rrect13% 0.9x0.8 smd paste+0 mask+0: 1(-0.7,-0.55) 2(0.7,-0.55) 3(0.7,0.55) 4(-0.7,0.55)
  silkscreen extent -1.9,-1.35 1.05,1.35, body extent -1.25,-1.05 1.25,1.05, height 0.25
FP-ERA-1AEB103C_0201-IPC_C [mil]
  rrect38% 13.94x10.34 smd paste+0 mask+0: 1(-10.01,0) 2(10.01,0)
  silkscreen extent -17,-22 17,22, body extent -12,-6 12,6, height 10
FP-ERJ-1GNF33R2C_0201-IPC_C [mil]
  rrect38% 13.94x10.34 smd paste+0 mask+0: 1(-10.01,0) 2(10.01,0)
  silkscreen extent -17,-22 17,22, body extent -12,-6 12,6, height 10
FP-ERJ-1GNF1003C_0201-IPC_C [mil]
  rrect38% 13.94x10.34 smd paste+0 mask+0: 1(-10.01,0) 2(10.01,0)
  silkscreen extent -17,-22 17,22, body extent -12,-6 12,6, height 10
FP-ERJ-1GNF1961C_0201-IPC_C [mil]
  rrect38% 13.94x10.34 smd paste+0 mask+0: 1(-10.01,0) 2(10.01,0)
  silkscreen extent -17,-22 17,22, body extent -21,-10 21,10, height 10
FP-ERJ-1GNF4701C_0201-IPC_C [mil]
  rrect38% 13.94x10.34 smd paste+0 mask+0: 1(-10.01,0) 2(10.01,0)
  body extent -12,-6 12,6, height 10
FP-ERJ-1GNF4991C_0201-IPC_C [mil]
  rrect38% 13.94x10.34 smd paste+0 mask+0: 1(-10.01,0) 2(10.01,0)
  silkscreen extent -17,-22 17,12, body extent -21,-10 21,10, height 10
FP-ERJ-1GNF7871C_0201-IPC_C [mil]
  rrect38% 13.94x10.34 smd paste+0 mask+0: 1(-10.01,0) 2(10.01,0)
  silkscreen extent -17,-12 17,12, body extent -12,-6 12,6, height 10
FP-ERJ-1GNF8252C_0201-IPC_C [mil]
  rrect38% 13.94x10.34 smd paste+0 mask+0: 1(-10.01,0) 2(10.01,0)
  silkscreen extent -17,-12 17,12, body extent -12,-6 12,6, height 10
FP-ERJ-1GNJ102C_0201-IPC_C [mil]
  rrect38% 13.94x10.34 smd paste+0 mask+0: 1(-10.01,0) 2(10.01,0)
  silkscreen extent -17,-22 17,22, body extent -21,-10 21,10, height 10
FP-ERJ-1GNJ221C_0201-IPC_C [mil]
  rrect38% 13.94x10.34 smd paste+0 mask+0: 1(-10.01,0) 2(10.01,0)
  silkscreen extent -17,-22 17,22, body extent -12,-6 12,6, height 10
FP-ERJ-1GNJ511C_0201-IPC_C [mil]
  rrect38% 13.94x10.34 smd paste+0 mask+0: 1(-10.01,0) 2(10.01,0)
  silkscreen extent -17,-22 17,22, body extent -21,-10 21,10, height 10
FP-ERJ-1GNJ751C_0201-IPC_C [mil]
  rrect38% 13.94x10.34 smd paste+0 mask+0: 1(-10.01,0) 2(10.01,0)
  silkscreen extent -17,-12 17,12, body extent -12,-6 12,6, height 10
FP-EXB-18VR000X_0502-MFG [mm]
  rrect57% 0.175x0.3 smd paste+0 mask+0: 1(-0.6,-0.275) 2(-0.2,-0.275) 3(0.2,-0.275) 4(0.6,-0.275) 5(0.6,0.275) 6(0.2,0.275) 7(-0.2,0.275) 8(-0.6,0.275)
  body extent -0.7,-0.3 0.7,0.3, height 0.45
FP-FW4000044Q_4-SMD-2.0x1.6mm-MFG [mm]
  rrect13% 0.9x0.8 smd paste+0 mask+0: 1(-0.7,-0.55) 2(0.7,-0.55) 3(0.7,0.55) 4(-0.7,0.55)
  silkscreen extent -1.83,-1.1 1,1.35, body extent -1.25,-1.05 1.25,1.05, height 0.25
"FP-GRM033R6YA104KE14D_0201 (0603 Metric)-IPC_C" [mil]
  rrect38% 13.94x10.34 smd paste+0 mask+0: 1(-10.01,0) 2(10.01,0)
  body extent -12,-6 12,6, height 13
"FP-GRM0335C1H8R0BA01D_0201 (0603 metric)-IPC_C" [mil]
  rrect38% 13.94x10.34 smd paste+0 mask+0: 1(-10.01,0) 2(10.01,0)
  body extent -21,-10 21,10, height 10
FP-GRPB052MWCN-RC_HDR10-MFG [mm]
  rrect9% 1.12x1.12 hole 0.7 paste-1000 mask+0: 1(-2.54,1.15)
  round 1.12 hole 0.7 paste-1000 mask+0: 2(-2.54,2.42) 3(-1.27,1.15) 4(-1.27,2.42) 5(0,1.15) 6(0,2.42) 7(1.27,1.15) 8(1.27,2.42) 9(2.54,1.15) 10(2.54,2.42)
  silkscreen extent -3.77,-0.7 3.42,1.17, body extent -3.18,-3.5 3.18,2.62, height 3.4
FP-M50-3930342_HDR3-MFG [mm]
  rrect9% 1.1x1.1 hole 0.6 paste-1000 mask+0: 1(-1.27,1)
  round 1.1 hole 0.6 paste-1000 mask+0: 2(0,1) 3(1.27,1)
  silkscreen extent -2.15,-0.6 2.15,2.09, body extent -1.91,-4.5 1.91,1.2, height 2.3
FP-M50-3930442_HDR4-RECOMMENDED_LAND_PATTERN [mm]
  rrect9% 1.1x1.1 hole 0.6 paste-1000 mask+0: 1(-1.905,1)
  round 1.1 hole 0.6 paste-1000 mask+0: 2(-0.635,1) 3(0.635,1) 4(1.905,1)
  body extent -2.54,-4.5 2.54,1.2, height 2.3
FP-MPZ2012S101ATD25_0805-MFG [mm]
  rrect13% 0.8x1.2 smd paste+0 mask+0: 1(-0.9,0) 2(0.9,0)
  silkscreen extent -0.13,-0.72 0.13,0.72, body extent -1.4,-0.82 1.4,0.82, height 0.25
FP-NRVB230LSFT1G_SOD-123F-MFG [mm]
  rrect8% 1.25x1.22 smd paste+0 mask+0: 1(-1.475,0) 2(1.475,0)
  silkscreen extent -2.8,-0.9 0.48,0.9, body extent -2.2,-1 2.2,1, height 0.25
"FP-RC0201JR-070RL_0201 (0603 Metric)-IPC_C" [mil]
  rrect38% 13.94x10.34 smd paste+0 mask+0: 1(-10.01,0) 2(10.01,0)
  body extent -12,-6 12,6, height 10
"FP-RC0201JR-070RL_0201 (0603 METRIC)-IPC_C" [mil]
  rrect38% 13.94x10.34 smd paste+0 mask+0: 1(-10.01,0) 2(10.01,0)
  body extent -12,-6 12,6, height 10
"FP-RC0201JR-070RL_0201 (0603 Metric)-MFG" [mm]
  rrect29% 0.35x0.4 smd paste+0 mask+0: 1(-0.325,0) 2(0.325,0)
  body extent -0.3,-0.15 0.3,0.15, height 0.26
FP-RR0306P-103-D_0201-IPC_C#1 [mil]
  rrect37% 13.31x10.73 smd paste+0 mask+0: 1(-10.52,0) 2(10.52,0)
  body extent -12,-6 12,6, height 10
FP-RR0306P-103-D_0201-IPC_C#2 [mil]
  rrect38% 13.94x10.34 smd paste+0 mask+0: 1(-10.52,0)
  rrect37% 13.31x10.73 smd paste+0 mask+0: 2(10.52,0)
  body extent -12,-6 12,6, height 10
IND_LQG15H [mm] "MuRata"
  rect 0.55x0.6 smd: 1(-0.475,0) 2(0.475,0)
  silkscreen extent -1.3,-0.3 -0.95,0.3, body extent -0.52,-0.27 0.52,0.27, height 0.55
MHNP_2-5 [mil]
  round 95 hole 100 unplated mask+5.5: ""(0,0)
  Keep-Out Layer circle w1: c0,0 r100
MHNP_M2_PANHEAD_PHILLIPS [mil]
  round 83 hole 88 unplated mask+5.5: ""(0,0)
  Keep-Out Layer circle w1: c0,0 r88
RGZ0048A [mm] "VQFN-48"
  rrect42% 0.6x0.24 smd: 1(-3.4,2.75) 2(-3.4,2.25) 3(-3.4,1.75) 4(-3.4,1.25) 5(-3.4,0.75) 6(-3.4,0.25) 7(-3.4,-0.25) 8(-3.4,-0.75) 9(-3.4,-1.25) 10(-3.4,-1.75) 11(-3.4,-2.25) 12(-3.4,-2.75) 25(3.4,-2.75) 26(3.4,-2.25) 27(3.4,-1.75) 28(3.4,-1.25) 29(3.4,-0.75) 30(3.4,-0.25) 31(3.4,0.25) 32(3.4,0.75) 33(3.4,1.25) 34(3.4,1.75) 35(3.4,2.25) 36(3.4,2.75)
  rrect42% 0.24x0.6 smd: 13(-2.75,-3.4) 14(-2.25,-3.4) 15(-1.75,-3.4) 16(-1.25,-3.4) 17(-0.75,-3.4) 18(-0.25,-3.4) 19(0.25,-3.4) 20(0.75,-3.4) 21(1.25,-3.4) 22(1.75,-3.4) 23(2.25,-3.4) 24(2.75,-3.4) 37(2.75,3.4) 38(2.25,3.4) 39(1.75,3.4) 40(1.25,3.4) 41(0.75,3.4) 42(0.25,3.4) 43(-0.25,3.4) 44(-0.75,3.4) 45(-1.25,3.4) 46(-1.75,3.4) 47(-2.25,3.4) 48(-2.75,3.4)
  rrect2% 5.15x5.15 smd paste-2.6: 49(0,0)
  body extent -3.5,-3.5 3.5,3.5, height 1
RNF0026C [mm] "QFN, 26-Leads, Body 4x4.5mm, Pitch 0.5mm"
  rrect25% 0.6x0.4 smd paste-0.3: 1(-1.9,1.825) 8(-1.9,-1.825) 14(1.9,-1.825) 21(1.9,1.825)
  rrect40% 0.6x0.25 smd paste+0: 2(-1.9,1.25) 3(-1.9,0.75) 4(-1.9,0.25) 5(-1.9,-0.25) 6(-1.9,-0.75) 7(-1.9,-1.25) 15(1.9,-1.25) 16(1.9,-0.75) 17(1.9,-0.25) 18(1.9,0.25) 19(1.9,0.75) 20(1.9,1.25)
  rrect40% 0.25x1.82 smd paste-1: 9(-1,-1.54) 10(-0.5,-1.54) 11(0,-1.54) 12(0.5,-1.54) 13(1,-1.54) 22(1,1.54) 23(0.5,1.54) 24(0,1.54) 25(-0.5,1.54) 26(-1,1.54)
  rrect15% 2.24x0.66 smd paste-1: 27(0,0)
  rrect33% 0.6x0.3 on Top Paste: ""(-1.9,1.775) ""(-1.9,-1.775) ""(1.9,1.775) ""(1.9,-1.775)
  rrect33% 0.3x0.825 on Top Paste: ""(-1.575,2.037) ""(-1.575,-2.037) ""(1.575,2.037) ""(1.575,-2.037)
  rrect40% 0.25x0.81 on Top Paste: ""(-1,1.035) ""(-1,2.045) ""(-1,-2.045) ""(-1,-1.035) ""(-0.5,2.045) ""(-0.5,1.035) ""(-0.5,-1.035) ""(-0.5,-2.045) ""(0,2.045) ""(0,1.035) ""(0,-1.035) ""(0,-2.045) ""(0.5,2.045) ""(0.5,1.035) ""(0.5,-1.035) ""(0.5,-2.045) ""(1,1.035) ""(1,2.045) ""(1,-2.045) ""(1,-1.035)
  rrect15% 0.98x0.66 on Top Paste: ""(-0.59,0) ""(0.59,0)
  Top Layer region: -1.775,1.675 -1.775,2.4 -1.771,2.419 -1.76,2.435 -1.744,2.446 -1.725,2.45 -1.725,2.45 -1.475,2.45 -1.456,2.446 -1.44,2.435 -1.429,2.419 -1.425,2.4 -1.425,2.4 -1.425,1.675 -1.429,1.656 -1.44,1.64 -1.456,1.629 -1.475,1.625 -1.475,1.625 -1.725,1.625 -1.744,1.629 -1.76,1.64 -1.771,1.656 -1.775,1.675
  Top Layer region: 1.425,1.675 1.425,2.4 1.429,2.419 1.44,2.435 1.456,2.446 1.475,2.45 1.475,2.45 1.725,2.45 1.744,2.446 1.76,2.435 1.771,2.419 1.775,2.4 1.775,2.4 1.775,1.675 1.771,1.656 1.76,1.64 1.744,1.629 1.725,1.625 1.725,1.625 1.475,1.625 1.456,1.629 1.44,1.64 1.429,1.656 1.425,1.675
  Top Layer region: 1.425,-2.4 1.425,-1.675 1.429,-1.656 1.44,-1.64 1.456,-1.629 1.475,-1.625 1.475,-1.625 1.725,-1.625 1.744,-1.629 1.76,-1.64 1.771,-1.656 1.775,-1.675 1.775,-1.675 1.775,-2.4 1.771,-2.419 1.76,-2.435 1.744,-2.446 1.725,-2.45 1.725,-2.45 1.475,-2.45 1.456,-2.446 1.44,-2.435 1.429,-2.419 1.425,-2.4
  Top Layer region: -1.775,-2.4 -1.775,-1.675 -1.771,-1.656 -1.76,-1.64 -1.744,-1.629 -1.725,-1.625 -1.725,-1.625 -1.475,-1.625 -1.456,-1.629 -1.44,-1.64 -1.429,-1.656 -1.425,-1.675 -1.425,-1.675 -1.425,-2.4 -1.429,-2.419 -1.44,-2.435 -1.456,-2.446 -1.475,-2.45 -1.475,-2.45 -1.725,-2.45 -1.744,-2.446 -1.76,-2.435 -1.771,-2.419 -1.775,-2.4
  silkscreen extent -2.45,-2.7 2.45,2.7, body extent -2,-2.25 2,2.25, height 0.9
RSE0010A [mm] "QFN, 10-Leads, Body 1.5x2mm, Pitch 0.5mm, TI Recommended"
  rect 0.55x0.2 smd: 1(-0.675,0.75) 2(-0.675,0.25) 3(-0.675,-0.25) 4(-0.675,-0.75) 6(0.675,-0.75) 7(0.675,-0.25) 8(0.675,0.25) 9(0.675,0.75)
  rect 0.3x0.6 smd: 5(0,-0.9) 10(0,0.9)
  silkscreen extent -1.07,-1.17 0.77,1.18, body extent -0.77,-1.02 0.78,1.03, height 0.61
RSV0016A [mm] "QFN, 16-Leads, Body 1.8x2.6mm, Pitch 0.4mm, TI Recommended"
  rect 0.7x0.2 smd: 1(-0.75,0.6)
  rect 0.6x0.2 smd: 2(-0.8,0.2) 3(-0.8,-0.2) 4(-0.8,-0.6) 9(0.8,-0.6) 10(0.8,-0.2) 11(0.8,0.2) 12(0.8,0.6)
  rect 0.2x0.6 smd: 5(-0.6,-1.2) 6(-0.2,-1.2) 7(0.2,-1.2) 8(0.6,-1.2) 13(0.6,1.2) 14(0.2,1.2) 15(-0.2,1.2) 16(-0.6,1.2)
  silkscreen extent -1.08,-1.33 1.08,1.45, body extent -0.92,-1.32 0.92,1.33, height 0.56
RUT0012A [mm] "QFN, 12-Leads, Body 1.7x2mm, Pitch 0.4mm, TI Recommended"
  rrect50% 0.7x0.2 smd: 1(-0.7,0.8) 2(-0.7,0.4) 3(-0.7,0) 4(-0.7,-0.4) 5(-0.7,-0.8) 7(0.7,-0.8) 8(0.7,-0.4) 9(0.7,0) 10(0.7,0.4) 11(0.7,0.8)
  rrect50% 0.2x0.7 smd: 6(0,-0.85) 12(0,0.85)
  silkscreen extent -0.9,-1.2 0.9,1.2, body extent -0.85,-1 0.85,1, height 0.55
Samtec_QSH-030-01-X-D-A [mm] "Receptacle, 0.5 mm, 30x2, TH"
  rect 2.27x0.279 smd: 1(-2.865,7.25) 2(2.865,7.25) 3(-2.865,6.75) 4(2.865,6.75) 5(-2.865,6.25) 6(2.865,6.25) 7(-2.865,5.75) 8(2.865,5.75) 9(-2.865,5.25) 10(2.865,5.25) 11(-2.865,4.75) 12(2.865,4.75) 13(-2.865,4.25) 14(2.865,4.25) 15(-2.865,3.75) 16(2.865,3.75) 17(-2.865,3.25) 18(2.865,3.25) 19(-2.865,2.75) 20(2.865,2.75) 21(-2.865,2.25) 22(2.865,2.25) 23(-2.865,1.75) 24(2.865,1.75) 25(-2.865,1.25) 26(2.865,1.25) 27(-2.865,0.75) 28(2.865,0.75) 29(-2.865,0.25) 30(2.865,0.25) 31(-2.865,-0.25) 32(2.865,-0.25) 33(-2.865,-0.75) 34(2.865,-0.75) 35(-2.865,-1.25) 36(2.865,-1.25) 37(-2.865,-1.75) 38(2.865,-1.75) 39(-2.865,-2.25) 40(2.865,-2.25) 41(-2.865,-2.75) 42(2.865,-2.75) 43(-2.865,-3.25) 44(2.865,-3.25) 45(-2.865,-3.75) 46(2.865,-3.75) 47(-2.865,-4.25) 48(2.865,-4.25) 49(-2.865,-4.75) 50(2.865,-4.75) 51(-2.865,-5.25) 52(2.865,-5.25) 53(-2.865,-5.75) 54(2.865,-5.75) 55(-2.865,-6.25) 56(2.865,-6.25) 57(-2.865,-6.75) 58(2.865,-6.75) 59(-2.865,-7.25) 60(2.865,-7.25)
  round 0 hole 1.02 unplated: MH1(2.67,10.065) MH2(2.67,-10.065)
  rect 0.43x2.54 smd: MP1(0,8.065) MP4(0,-8.065)
  rect 0.43x4.7 smd: MP2(0,3.175) MP3(0,-3.175)
  silkscreen extent -3.9,-10.66 3.62,10.66, body extent -3.75,-10.64 3.75,10.67, height 3.25
SW_218-4LPST [mil] "CTS Components"
  rect 50x30 smd: 1(-150,75) 2(-150,25) 3(-150,-25) 4(-150,-75) 5(150,-75) 6(150,-25) 7(150,25) 8(150,75)
  silkscreen extent -114,-123 114,123, body extent -166,-123 166,123, height 104
SW_B3U-1000P [mm] "OMRON"
  rect 0.8x1.7 smd: 1(-1.7,0) 2(1.7,0)
  silkscreen extent -1.5,-1.25 1.5,1.25, body extent -1.5,-1.25 1.5,1.25, height 1.75
TP_25MIL-SMT [mil]
  round 25 smd mask-2.5: 1(0,0)
TP_SM_1MM [mm] "1mm Test Point, SMT"
  round 1 smd paste-0.5: 1(0,0)
TP_VIA_060RND040 [mil] "TP_VIA_060RND040"
  round 60 hole 40: 1(0,0)
WSON-8L_6x5MM_EP [mm] "SMD, 8-Leads, Body 6x5mm, Pitch 1.27mm"
  rrect25% 0.8x0.4 smd: 1(-2.8,1.905) 2(-2.8,0.635) 3(-2.8,-0.635) 4(-2.8,-1.905) 5(2.8,-1.905) 6(2.8,-0.635) 7(2.8,0.635) 8(2.8,1.905)
  rrect3% 3.4x4 smd paste-3: 9(0,0)
  rrect50% 1.468x1.698 on Bottom Paste: ""(-0.834,-0.949) ""(-0.834,0.949) ""(0.834,-0.949) ""(0.834,0.949)
  silkscreen extent -3.2,-2.7 3.2,2.7, body extent -3.05,-2.55 3.05,2.55, height 0.8

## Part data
A1: library part CMP-0087189-1, "RF ANT 2.4GHZ CHIP SOLDER SMD", Manufacturer="TDK Corporation"
C1 C4 C50 C51 C52 C53 C55 C59 C62 C65 C70 C76 C78 C82 C112 C113 C121: library part CMP-0008017-2, "CAP, CERM, 10 uF, 10 V, +/- 10%, X7R, 0805", Cap_Case=0805, Manufacturer=MuRata, Supplier Part Number 1=490-10674-1-ND, TempCo=X7R, Tolerance_%=10%, Value1=Unknown, Value2=10V, ValueDisplayed=10uF
C2 C3 C91 C92 C101 C126 C130: library part CMP-0006351-2, "CAP, CERM, 0.1 uF, 16 V, +/- 10%, X7R, 0402", Cap_Case=0402, Manufacturer=MuRata, Supplier Part Number 1=490-4759-2-ND, TempCo=X7R, Tolerance_%=10%, Value1=Unknown, Value2=16V, ValueDisplayed=0.1uF
C5 C11 C15 C16 C24 C115 C116 C129: library part CMP-0086446-1, "1µF ±20% 16V Ceramic Capacitor X5R 0201", Manufacturer="Samsung Electro-Mechanics", TempCo=15%, Tolerance_%=20%
C6 C9 C10 C12 C13 C25 C26 C27 C35 C36 C37 C40 C43 C72 C86 C105 C107 C108 C109 C114 C117 C118 C119 C120 C123 C127 C128: library part CMP-0086440-1, "Cap Ceramic 0.1uF 35V X5R 10% Pad SMD 0201 85C T/R", Manufacturer="Murata Electronics North America", TempCo=15%, Tolerance_%=10%
C7 C42 C122: library part CMP-0006339-4, "CAP, CERM, 10 uF, 10 V, +/- 20%, X5R, 0402", Cap_Case=0402, Manufacturer="Samsung Electro-Mechanics", TempCo=X5R, Tolerance_%=20%, Value1=Unknown, Value2=10V, ValueDisplayed=10uF
C8 C125: library part CMP-0086445-1, "CAP CER 10000PF 25V X5R 0201", Manufacturer="Samsung Electro-Mechanics America, Inc", TempCo=15%, Tolerance_%=10%
C14 C71: library part CMP-0090493-1, "Cap Ceramic 4.7pF 50V C0G 0.25pF Pad SMD 0201 125°C Automotive T/R", Manufacturer=TDK, Operating Temperature Range="-55°C to +125°C", TempCo=30ppm/°C, Temperature Characteristic=C0G, ValueDisplayed=4.7pF
C17 C18: library part CMP-0086441-1, "Cap Ceramic 8pF 50V C0G 0.1pF SMD 0201 125°C Paper T/R", Manufacturer=Murata, TempCo=30ppm/°C
C19 C20 C38 C39: library part CMP-0087190-1, "CAP CER 12PF 25V C0G/NP0 0201", Manufacturer="Johanson Technology Inc.", TempCo=30ppm/°C, Tolerance_%=5%
C21 C93: library part CMP-0006345-2, "CAP, CERM, 12 pF, 50 V, +/- 5%, C0G/NP0, 0402", Cap_Case=0402, Manufacturer="Samsung Electro-Mechanics", Supplier Part Number 1=1276-1178-1-ND, TempCo=C0G/NP0, Tolerance_%=5%, Value1=Unknown, Value2=50V, ValueDisplayed=12pF
C22 C23 C41: library part CMP-0085178-1, "CAP, CERM, 1 pF, 50 V,+/- 25%, C0G/NP0, AEC-Q200 Grade 1, 0402", Cap_Case=0402, Manufacturer=MuRata, TempCo=C0G/NP0, Tolerance_%=25%, Value2=50V, ValueDisplayed=1pF
C28 C29: library part CMP-0089043-4, "CAP CER 22UF 6.3V X5R 0402", Manufacturer="Samsung Electro-Mechanics", TempCo=15%, Tolerance_%=20%, ValueDisplayed=22uF
C30 C56 C57 C58 C60 C61 C63 C64 C66 C67 C68 C80 C81 C84 C85 C87 C88 C94 C95 C96 C97 C98: library part CMP-0078265-1, "CAP, CERM, 0.22 µF, 16 V,+/- 10%, X7R, AEC-Q200 Grade 1, 0402", Cap_Case=0402, Manufacturer=MuRata, Supplier Part Number 1=490-10671-1-ND, TempCo=X7R, Tolerance_%=10%, Value2=16V, ValueDisplayed=0.22µF
C31 C32 C33 C34: library part CMP-0085511-1, "CAP, CERM, 390 pF, 50 V,+/- 5%, C0G/NP0, AEC-Q200 Grade 1, 0402", Cap_Case=0402, Manufacturer=TDK, TempCo=C0G/NP0, Tolerance_%=5%, Value2=50V, ValueDisplayed=390pF
C44 C45 C46 C47 C48 C49 C54 C73 C75 C77 C111 C124 C131: library part CMP-0091983-1, "22µF ±20% 6.3V Ceramic Capacitor X7T 0805 (2012 Metric)", Digikey Part Number=445-CGA4J1X7T0J226M125ACCT-ND, Manufacturer=TDK, Mouser Part Number=810-CGA4J1X7T0J226M1, Operating Temperature Range="-55°C to +125°C", TempCo=+22/-33%, Temperature Characteristic=X7T, Tolerance_%=20%, ValueDisplayed=22uF
C69: library part CMP-0006330-2, "CAP, CERM, 0.047 uF, 50 V, +/- 10%, X7R, AEC-Q200 Grade 1, 0402", Cap_Case=0402, Manufacturer=TDK, Supplier Part Number 1=445-6897-1-ND, TempCo=X7R, Tolerance_%=10%, Value1="0.06407 ohm", Value2=50V, ValueDisplayed=0.047uF
C74 C79 C83 C102 C103: library part CMP-0007134-5, "CAP, CERM, 2.2 uF, 6.3 V, +/- 10%, X7R, AEC-Q200 Grade 1, 0603", Cap_Case=0603, Manufacturer=MuRata, Supplier Part Number 1=490-5316-1-ND, TempCo=X7R, Tolerance_%=10%, Value1=Unknown, Value2=6.3V, ValueDisplayed=2.2uF
C89 C90 C100: library part CMP-0007136-5, "CAP, CERM, 1 uF, 16 V, +/- 10%, X7R, AEC-Q200 Grade 1, 0603", Cap_Case=0603, Manufacturer=MuRata, Supplier Part Number 1=490-5241-6-ND, TempCo=X7R, Tolerance_%=10%, Value1=Unknown, Value2=16V, ValueDisplayed=1uF
C99 C104: library part CMP-0086306-1, "CAP, CERM, 1.8 pF, 50 V,+/- 6%, C0G/NP0, 0402", Cap_Case=0402, Manufacturer=MuRata, TempCo=C0G/NP0, Tolerance_%=6%, Value2=50V, ValueDisplayed=1.8pF
C106 C110: library part CMP-0006692-2, "CAP, CERM, 4700 pF, 50 V, +/- 10%, X7R, 0402", Cap_Case=0402, Manufacturer=MuRata, Supplier Part Number 1=490-1308-1-ND, TempCo=X7R, Tolerance_%=10%, Value1=Unknown, Value2=50V, ValueDisplayed=4700pF
D1: library part CMP-0090508-1, "Diode Schottky 30V 2A Surface Mount SOD-123FL", Digikey Part Number=NRVB230LSFT1GOSCT-ND, Forward Current=2A, Manufacturer="ON Semiconductor", Max Surge Forward Current=40A, Mouser Part Number=863-NRVB230LSFT1G, Operating Temperature Range="-55°C to +125°C", Peak Reverse Current=1mA
FID1 FID2 FID3 FID4 FID5 FID6: library part CMP-0077181-1, "Fiducial mark.  There is nothing to buy or mount.", Manufacturer=N/A
FL2 FL3 FL12 FL22: library part CMP-0078934-1, "Inductor, Ferrite Bead, Ferrite, 2.2 A, 0.035 ohm, AEC-Q200 Grade 1, SMD", Manufacturer=MuRata, Supplier Part Number 1=490-16506-1-ND, Value1="0.035 ohm", Value2=2.2A
J1: library part CMP-0055293-1, "Connector, Receptacle, Micro-USB Type B, R/A, Bottom Mount SMT", Manufacturer=Molex, Supplier Part Number 1=WM1399CT-ND
J2 J11: library part CMP-0075524-1, "Receptacle, 0.5 mm, 30x2, Gold, TH", Color=Black, Manufacturer=Samtec, Supplier Part Number 1=SAM8180-ND
J3: library part CMP-0087187-1, "CONN HDR 1.27MM R/A AU 4POS", Current_A=1A, Manufacturer="Harwin Inc."
J4 J6: library part CMP-0086453-1, "Easy-On™ Type FFC/FPC Connector, Right-Angle, Surface Mount, ZIF, Bottom Contact Style, 1.10mm Mated Height, 10 Circuits", Manufacturer=Molex
J5: library part CMP-0081851-1, "DC Power Jack, R/A, TH", Color=Black, Current_A=5A, Manufacturer="CUI Inc.", Supplier Part Number 1=CP-051AH-ND, Voltage_V=24V
J7: library part CMP-0087786-1, "CONN HEADER R/A 10POS 1.27MM", Current_A=1A, Manufacturer=Sullins
J8 J10: library part CMP-0087785-1, "CONN HEADER R/A 3POS 1.27MM", Current_A=1A, Manufacturer=Harwin
L1 L6: library part CMP-0058626-1, "Inductor, Multilayer, Air Core, 2.4 nH, 0.3 A, 0.15 ohm, SMD", Manufacturer=MuRata, Supplier Part Number 1=LQG15HS2N4S02D-ND, Value1="0.15 ohm", Value2=0.3A, ValueDisplayed=2.4nH
L2 L3 L4 L5: library part CMP-0058944-1, "Inductor, Shielded, 470 nH, 4.7 A, 0.021 ohm, SMD", Manufacturer="MuRata Toko", Value1="0.021 ohm", Value2=4.7A, ValueDisplayed=470nH
L7: library part CMP-0062727-1, "Inductor, Multilayer, Ferrite, 6.8 uH, 0.11 A, 0.25 ohm, SMD", Manufacturer=TDK, Supplier Part Number 1=445-6761-1-ND, Value1="0.25 ohm", Value2=0.11A, ValueDisplayed=6.8uH
L8: library part CMP-0003349-2, "Ferrite Bead, 1500 ohm @ 100 MHz, 0.5 A, 0603", Manufacturer=MuRata, Supplier Part Number 1=490-5216-1-ND, Value1="0.5 ohm", Value2=0.5A, ValueDisplayed="1500 ohm"
L9 L10: library part CMP-0058624-1, "Inductor, Multilayer, Air Core, 2 nH, 0.3 A, 0.1 ohm, SMD", Manufacturer=MuRata, Supplier Part Number 1=490-6569-1-ND, Value1="0.1 ohm", Value2=0.3A, ValueDisplayed=2nH
L11 L13 L15 L16: library part CMP-0089947-1, "100 Ohms @ 100MHz 1 Power Line Ferrite Bead 0805 (2012 Metric) 4A 20mOhm", Digikey Part Number=445-172903-1-ND, Impedance At Frequency="100O @ 100MHz", Manufacturer=TDK, Mouser Part Number=810-MPZ2012S101ATD25, Operating Temperature Range="-55°C to +125°C", Test Frequency=100MHz, Tolerance_%=25%
L12 L14: library part CMP-0077879-1, "Ferrite Bead, 120 ohm @ 100 MHz, 1.9 A, 0603", Manufacturer=MuRata, Supplier Part Number 1=490-13261-1-ND, Value1="0.04 ohm", Value2=1.9A, ValueDisplayed="120 ohm"
LD1 LD2 LD3 LD4 LD5 LD6: library part CMP-0067682-2, "LED, Green, SMD", Color=Green, Manufacturer=Kingbright, Power_TotalModule=75mW, Value1=0.075W, Value2=2.1V
Q1: library part CMP-0087176-1, "MOSFET N-CH 100V 170MA SOT23-3", Manufacturer="Diodes Incorporated"
R1 R18 R20 R77 R78 R80 R81 R82 R93 R94 R95 R96 R98 R104 R110 R118 R122 R124 R125 R134 R177 R178: library part CMP-0088002-1, "10 kOhms ±0.5% 0.05W, 1/20W Chip Resistor 0201 (0603 Metric)  Thin Film", Manufacturer=Susumu, Power_W=50mW, TempCo=25ppm/°C, Tolerance_%=0.5%
R2 R28 R31 R32 R41 R60 R61 R62 R63 R103: library part CMP-0065361-1, "RES, 0, 5%, .05 W, AEC-Q200 Grade 0, 0201", Manufacturer=Panasonic, Power_W=50mW, Supplier Part Number 1=P15979CT-ND, TempCo=ppm/C, Tolerance_%=5%, Value2=.05W, Value_Code=0000, ValueDisplayed=0
R3 R7 R8 R19 R21 R22 R23 R35 R36 R43 R44 R45 R59 R65 R83 R84 R85: library part CMP-0090084-1, "RES SMD 10K OHM 0.1% 1/20W 0201", Digikey Part Number=P10KBXCT-ND, Manufacturer=Panasonic, Mouser Part Number=667-ERA-1AEB103C, Operating Temperature Range="-55°C to +155°C", Power_W=50mW, TempCo=25ppm/°C, Tolerance_%=0.1%
R4 R5 R9 R37: library part CMP-0090298-1, "100 kOhms ±1% 0.05W, 1/20W Chip Resistor 0201 (0603 Metric) Automotive AEC-Q200 Thick Film", Digikey Part Number=P122655CT-ND, Manufacturer="Panasonic Electronic Components", Mouser Part Number=667-ERJ-1GNF1003C, Operating Temperature Range="-55°C to +125°C", Power_W=50mW, TempCo=200ppm/°C, Tolerance_%=1%
R6 R46 R47 R48 R49: library part CMP-0089575-2, "Res Thick Film 0201 33.2 Ohm 1% 0.05W(1/20W) ±200ppm/C Pad SMD Automotive T/R", Digikey Part Number=P122945CT-ND, Manufacturer=Panasonic, Mouser Part Number=667-ERJ-1GNF33R2C, Operating Temperature Range="-55°C to +125°C", Power_W=50mW, TempCo=200ppm/°C, Tolerance_%=1%
R10 R11 R88 R130 R132 R133 R135 R137 R138 R140: library part CMP-0087185-1, "RES SMD 20 OHM 1% 1/20W 0201", Manufacturer=Yageo, Power_W=50mW, TempCo=200ppm/°C, Tolerance_%=1%
R12 R14 R30 R51 R57 R58 R66 R67 R68 R70 R71 R72 R73 R74 R76 R86 R87 R90 R91 R97 R99 R100 R101 R102 R105 R106 R112 R113 R115 R116 R120 R121 R123 R127 R128 R129 R131 R136 R139 R142 R143 R144 R145 R146 R147 R148 R149 R150 R151 R152 R153 R154 R155 R157 R160 R161 R166 R168 R182 R183 R184 R185 R186 R187 R188 R189 R190: library part CMP-0086442-2, "RES SMD 0 OHM JUMPER 1/20W 0201", Manufacturer=Yageo, Power_W=50mW, TempCo=200ppm/°C, Tolerance_%=5%
R13 R17 R42 R111: library part CMP-0027072-1, "RES, 220, 5%, 0.05 W, 0201", Manufacturer="Yageo America", Power_W=50mW, Supplier Part Number 1=311-220NCT-ND, TempCo="200 ppm/C", Tolerance_%=5%, Value2=0.05W, Value_Code=220R, ValueDisplayed=220
R15: library part CMP-0090501-1, "220 Ohms ±5% 0.05W, 1/20W Chip Resistor 0201 (0603 Metric) Automotive AEC-Q200 Thick Film", Digikey Part Number=P123276CT-ND, Manufacturer="Panasonic Electronic Components", Mouser Part Number=667-ERJ-1GNJ221C, Operating Temperature Range="-55°C to +125°C", Power_W=50mW, TempCo=200ppm/°C, Tolerance_%=5%
R16: library part CMP-0027880-1, "RES, 7.87 k, 1%, 0.05 W, 0201", Manufacturer="Yageo America", Power_W=50mW, Supplier Part Number 1=YAG2807CT-ND, TempCo="200 ppm/C", Tolerance_%=1%, Value2=0.05W, Value_Code=7k87, ValueDisplayed=7.87k
R24: library part CMP-0087183-1, "RES SMD 200 OHM 1% 1/5W 0402", Manufacturer="Vishay Dale", Power_W=200mW, TempCo=100ppm/°C, Tolerance_%=1%
R25 R26 R33 R34 R40 R64: library part CMP-0090497-1, "4.99 kOhms ±1% 0.05W, 1/20W Chip Resistor 0201 (0603 Metric) Automotive AEC-Q200 Thick Film", Digikey Part Number=P123046CT-ND, Manufacturer="Panasonic Electronic Components", Mouser Part Number=667-ERJ-1GNF4991C, Operating Temperature Range="-55°C to +125°C", Power_W=50mW, TempCo=200ppm/°C, Tolerance_%=1%
R27 R107 R108: library part CMP-0027137-1, "RES, 510, 5%, 0.05 W, 0201", Manufacturer="Yageo America", Power_W=50mW, Supplier Part Number 1=YAG2907CT-ND, TempCo="200 ppm/C", Tolerance_%=5%, Value2=0.05W, Value_Code=510R, ValueDisplayed=510
R29 R89 R92: library part CMP-0027261-3, "RES, 100 k, 1%, 0.05 W, 0201", Manufacturer=Vishay-Dale, Power_W=50mW, Supplier Part Number 1=541-100KAABCT-ND, TempCo="100 ppm/C", Tolerance_%=1%, Value2=0.05W, Value_Code=100k
R38 R69 R141: library part CMP-0027745-1, "RES, 4.99 k, 1%, 0.05 W, 0201", Manufacturer="Yageo America", Power_W=50mW, Supplier Part Number 1=YAG2712CT-ND, TempCo="200 ppm/C", Tolerance_%=1%, Value2=0.05W, Value_Code=4k99, ValueDisplayed=4.99k
R39: library part CMP-0090502-1, "510 Ohms ±5% 0.05W, 1/20W Chip Resistor 0201 (0603 Metric) Automotive AEC-Q200 Thick Film", Digikey Part Number=P123339CT-ND, Manufacturer="Panasonic Electronic Components", Mouser Part Number=667-ERJ-1GNJ511C, Operating Temperature Range="-55°C to +125°C", Power_W=50mW, TempCo=200ppm/°C, Tolerance_%=5%
R50 R75: library part CMP-0090500-1, "1 kOhms ±5% 0.05W, 1/20W Chip Resistor 0201 (0603 Metric) Automotive AEC-Q200 Thick Film", Digikey Part Number=P123221CT-ND, Manufacturer="Panasonic Electronic Components", Mouser Part Number=667-ERJ-1GNJ102C, Operating Temperature Range="-55°C to +125°C", Power_W=50mW, TempCo=200ppm/°C, Tolerance_%=5%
